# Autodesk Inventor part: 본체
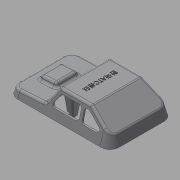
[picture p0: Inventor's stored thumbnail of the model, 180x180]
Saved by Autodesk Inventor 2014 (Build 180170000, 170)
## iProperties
Created: 2015-05
Part Number: 본체
Material: Generic
Document SubType Name: Modeling
Designer: Administrator
Density: 1 g/cm^3
Appearance: Default
Author: Administrator
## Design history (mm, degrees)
sketch "스케치2"
  geometry: L1 (-49, 38)-(49, 38); L2 (61, 26)-(61, -26); L3 (49, -38)-(-49, -38); L4 (-61, -26)-(-61, 26); L5 (-61, 38)-(61, -38); L6 (61, 38)-(-61, -38); A1 r 12 centre (-49, 26) between (-49, 38) and (-61, 26); A2 r 12 centre (-49, -26) between (-61, -26) and (-49, -38); A3 r 12 centre (49, -26) between (49, -38) and (61, -26); A4 r 12 centre (49, 26) between (61, 26) and (49, 38); 1 further point
  constraints: 12 end point, 8 point on circle, 8 point on line, 8 tangent, 4 centre point, 3 equal radius, 2 midpoint, 2 parallel, 1 horizontal, 1 perpendicular
  dimensions: "d0" = 122 distance of L5.end L6.end; "d1" = 76 distance of L6.start L5.end; "d2" = 12 radius of A1
extrude "돌출1" new body sketch "스케치2" distance "d3" = 30; taper "d4" = -15 deg
sketch "스케치3"
  geometry: L1 (-31, 30)-(-61, 30); L2 (-61, 30)-(-61, 10); L3 (-61, 10)-(-31, 30); L4 (49, 30)-(-49, 30) reference; 2 further points
  constraints: 6 end point, 1 collinear, 1 horizontal, 1 perpendicular, 1 vertical alignment
  dimensions: "d5" = 20 distance of L1.end L2.end; "d6" = 30 distance of L1.start L1.end
extrude "돌출2" cut sketch "스케치3" stored distance "d7" = 30; taper "d8" = 0 deg
sketch "스케치4"
  geometry: L1 (61, 8)-(19, 10.201); L2 (19, 10.201)-(6.628, 30); L3 (6.628, 30)-(61, 30); L4 (61, 30)-(61, 8); L5 (-49, 0)-(49, 0) reference; L6 (49, 30)-(-31, 30) reference; 3 further points
  constraints: 8 end point, 1 collinear, 1 horizontal, 1 midpoint, 1 perpendicular, 1 vertical alignment
  dimensions: "d10" = 8 distance from line of L5 L1.start; "d12" = 125 deg angle of L1 L2; "d13" = 3 deg angle of L5 L1; "d16" = 42 horizontal distance of L1.end L1.start
extrude "돌출3" cut sketch "스케치4" stored distance "d14" = 30; taper "d15" = 0 deg
sketch "스케치5"
  geometry: L1 (-39.881, 9.267)-(-39.881, 61.267) reference; L2 (-28.881, 48.267)-(-8.881, 48.267); L3 (-8.881, 48.267)-(-8.881, 22.267); L4 (-8.881, 22.267)-(-28.881, 22.267); L5 (-28.881, 22.267)-(-28.881, 48.267); 3 further points
  constraints: 8 end point, 2 midpoint, 2 parallel, 1 horizontal, 1 horizontal alignment, 1 perpendicular
  dimensions: "d17" = 11 distance between parallel lines of L1 L5; "d18" = 26 distance of L4.end L2.start; "d19" = 20 distance of L2.start L2.end
extrude "돌출4" join sketch "스케치5" distance "d20" = 5; taper "d21" = 0 deg
fillet "모깎기1" dims "d22" = 3
fillet "모깎기2" dims "d23" = 3
fillet "모깎기3" dims "d24" = 3
fillet "모깎기4" dims "d25" = 3
sketch "스케치6"
  geometry: L1 (4.965, 30)-(-30.092, 30) reference; L2 (18.172, 11.526)-(7.51, 28.59) reference; L3 (-31.756, 29.496)-(-50.664, 16.891) reference; L4 (2.194, 25)-(-17.77, 25); L5 (10.362, 14.59)-(4.738, 23.59); L6 (7.818, 10)-(-17.77, 10); L7 (-20.77, 13)-(-20.77, 22); L8 (-30.242, 24.496)-(-43.742, 15.496); L9 (-28.578, 25)-(-26.986, 25); L10 (-23.986, 22)-(-23.986, 13); L11 (-26.986, 10)-(-42.078, 10); A1 r 3 centre (7.818, 13) between (7.818, 10) and (10.362, 14.59); A2 r 3 centre (2.194, 22) between (4.738, 23.59) and (2.194, 25); A3 r 3 centre (-17.77, 22) between (-17.77, 25) and (-20.77, 22); A4 r 3 centre (-17.77, 13) between (-20.77, 13) and (-17.77, 10); A5 r 3 centre (-26.986, 13) between (-26.986, 10) and (-23.986, 13); A6 r 3 centre (-26.986, 22) between (-23.986, 22) and (-26.986, 25); A7 r 3 centre (-28.578, 22) between (-28.578, 25) and (-30.242, 24.496); A8 r 3 centre (-42.078, 13) between (-43.742, 15.496) and (-42.078, 10); 7 further points
  constraints: 16 end point, 16 point on circle, 16 tangent, 12 point on line, 8 centre point, 7 equal radius, 5 parallel, 3 perpendicular
  dimensions: "d26" = 5 distance between parallel lines of L4 L1; "d27" = 5 distance between parallel lines of L5 L2; "d28" = 34 distance of point (13.23, 10) point (-20.77, 10); "d29" = 15 distance of point (-20.77, 25) point (-20.77, 10); "d30" = 5 distance between parallel lines of L8 L3; "d31" = 5 distance between parallel lines of L9 L1; "d32" = 15 distance of point (-23.986, 25) point (-23.986, 10); "d33" = 28 distance of point (-51.986, 10) point (-23.986, 10); "d35" = 3 radius of A1
sketch "스케치7"
  geometry: L1 (61, 26)-(61, -26) reference; L2 (-49, 38)-(49, 38) reference; L3 (-61, -26)-(-61, 26) reference; L4 (49, -38)-(-49, -38) reference; A1 r 12 centre (49, 26) between (61, 26) and (49, 38) reference; A2 r 12 centre (-49, 26) between (-49, 38) and (-61, 26) reference; A3 r 12 centre (-49, -26) between (-61, -26) and (-49, -38) reference; A4 r 12 centre (49, -26) between (49, -38) and (61, -26) reference; 1 further point
feature "쉘1" dims "d34" = 2
extrude "돌출5" cut sketch "스케치6" stored distance "d36" = 5; taper "d37" = 0 deg
node "작업 평면1"
sketch "스케치8"
  geometry: A1 r 4 centre (21, 0) between (25, 0) and (17, 0); A2 r 4 centre (10, 0) between (14, 0) and (6, 0); 3 further points
  constraints: 4 point on circle, 2 centre point, 7 other
  dimensions: "d39" = 4 radius of A1; "d40" = 4 radius of A2; "d41" = 10 distance of A2.centre point (0, 0); "d42" = 11 distance of A2.centre A1.centre
extrude "돌출6" join sketch "스케치8" stored distance "d43" = 5; taper "d44" = 0 deg
chamfer "모따기1" distance "d45" = 1; stored, may be unused: second distance "d46" = 2, angle "d47" = 45 deg
sketch "스케치9"
  geometry: L1 (-4.965, -27.66)-(-4.965, 27.66) reference; L2 (61, -26)-(61, 26) reference; 3 further points
  constraints: 1 horizontal alignment, 1 midpoint, 1 other
  dimensions: "d48" = 50 distance from line of L2 point (11, 0)
feature "엠보싱1" sketch "스케치9" dims "d0" = 122, "d1" = 76, "d2" = 12, "d49" = 0.5, "d50" = 0
sketch "스케치10"
  geometry: L1 (58.929, 26)-(58.929, -26) reference; L2 (49, -35.929)-(-49, -35.929) reference; L3 (-58.929, -26)-(-58.929, 26) reference; L4 (-49, 35.929)-(49, 35.929) reference; L5 (49, 36.929)-(-49, 36.929); L6 (-59.929, 26)-(-59.929, -26); L7 (-49, -36.929)-(49, -36.929); L8 (59.929, -26)-(59.929, 26); A1 r 9.929 centre (49, -26) between (49, -35.929) and (58.929, -26) reference; A2 r 9.929 centre (-49, -26) between (-58.929, -26) and (-49, -35.929) reference; A3 r 9.929 centre (-49, 26) between (-49, 35.929) and (-58.929, 26) reference; A4 r 9.929 centre (49, 26) between (58.929, 26) and (49, 35.929) reference; A5 r 10.929 centre (-49, 26) between (-49, 36.929) and (-59.929, 26); A6 r 10.929 centre (-49, -26) between (-59.929, -26) and (-49, -36.929); A7 r 10.929 centre (49, -26) between (49, -36.929) and (59.929, -26); A8 r 10.929 centre (49, 26) between (59.929, 26) and (49, 36.929); 1 further point
  constraints: 8 end point, 8 point on circle, 4 centre point, 7 other
  dimensions: "d51" = 1 distance between parallel lines of L4 L5
extrude "돌출7" join sketch "스케치10" distance "d52" = 1; taper "d53" = 0 deg
sketch "스케치11"
  geometry: C1 r 3 at (0, 22); C2 r 3 at (-40, 0); C3 r 3 at (0, -22); C4 r 3 at (40, 0); 1 further point
  constraints: 4 centre point, 2 horizontal alignment, 2 vertical alignment
  dimensions: "d54" = 6 diameter of C3; "d55" = 6 diameter of C1; "d56" = 6 diameter of C2; "d57" = 6 diameter of C4; "d58" = 22 distance of C1.centre point (0, 0); "d59" = 44 distance of C1.centre C3.centre; "d60" = 40 distance of point (0, 0) C4.centre; "d61" = 40 distance of point (0, 0) C2.centre
extrude "돌출8" join sketch "스케치11" stored distance "d62" = 1; taper "d63" = 2 deg
node "작업 평면2"
sketch "스케치12"
  geometry: L1 (-44.994, -1)-(-34.994, -1); L2 (-34.994, -1)-(-34.994, 1); L3 (-34.994, 1)-(-44.994, 1); L4 (-44.994, 1)-(-44.994, -1); L5 (-44.994, -1)-(-34.994, 1); L6 (-34.994, -1)-(-44.994, 1); L7 (-5, 21)-(5, 21); L8 (5, 21)-(5, 23); L9 (5, 23)-(-5, 23); L10 (-5, 23)-(-5, 21); L11 (-5, 21)-(5, 23); L12 (5, 21)-(-5, 23); L13 (34.913, -1)-(44.913, -1); L14 (44.913, -1)-(44.913, 1); L15 (44.913, 1)-(34.913, 1); L16 (34.913, 1)-(34.913, -1); L17 (34.913, -1)-(44.913, 1); L18 (44.913, -1)-(34.913, 1); L19 (-5, -23)-(5, -23); L20 (5, -23)-(5, -21); L21 (5, -21)-(-5, -21); L22 (-5, -21)-(-5, -23); L23 (-5, -23)-(5, -21); L24 (5, -23)-(-5, -21); C1 r 3.978 at (0, -22) reference; C2 r 3.978 at (0, 22) reference; 3 further points; 2 other entities
  constraints: 48 end point, 8 midpoint, 8 parallel, 4 horizontal, 4 perpendicular, 2 other
  dimensions: "d65" = 2 distance of L1.end L2.end; "d66" = 10 distance of L2.end L3.end; "d67" = 10 distance of L7.start L7.end; "d68" = 2 distance of L7.end L8.end; "d69" = 10 distance of L14.end L15.end; "d70" = 2 distance of L13.end L14.end; "d71" = 10 distance of L20.end L21.end; "d72" = 2 distance of L19.end L20.end
extrude "돌출9" join sketch "스케치12" stored distance "d73" = 2; taper "d74" = 2.5 deg
sketch "스케치18"
  geometry: C1 r 3 at (0, 0) reference; C2 r 3 at (-40, 22) reference; C3 r 3 at (0, 44) reference; C4 r 3 at (40, 22) reference; 5 further points
  constraints: 4 coincident
hole "구멍1" sketch "스케치18" at (-40, 22), (0, 0), (40, 22), (0, 44) diameter "d94" = 3.242; stored, may be unused: countersink angle "d98" = 90 deg, drill point angle "d100" = 118 deg; dims "d95" = 9, "d96" = 4, "d97" = 2, "d99" = 11
sketch "스케치19"
  geometry: L1 (34.994, 2)-(34.54, 12.391) reference; L2 (31.021, 12.575)-(45.002, 11.843) reference; L3 (44.994, 2)-(45.42, 11.762) reference; L4 (-30.092, 30)-(4.965, 30) reference; L5 (34.994, 2)-(33.149, 12.464); L6 (44.994, 2)-(46.348, 9.68); A1 r 5 centre (50.994, 11.529) between (46.027, 10.954) and (50.732, 6.535) reference; A2 r 1 centre (45.034, 10.84) between (46.027, 10.954) and (45.086, 11.838) reference; 1 further point
  constraints: 4 end point, 1 point on circle, 1 point on line
  dimensions: "d101" = 80 deg angle of L4 L5; "d102" = 100 deg angle of L4 L6
extrude "돌출15" join sketch "스케치19" stored distance "d103" = 2; taper "d104" = 0 deg
sketch "스케치20"
  geometry: L1 (-44.913, 2)-(-45.605, 17.86) reference; L2 (-34.913, 2)-(-33.879, 25.677) reference; L3 (-30.092, 30)-(4.965, 30) reference; L4 (-34.913, 2)-(-30.333, 27.97); L5 (-44.913, 2)-(-47.488, 16.604); L6 (-49.555, 15.226)-(-30.646, 27.832) reference; A1 r 1 centre (-30.092, 27) between (-30.092, 28) and (-30.646, 27.832) reference; 1 further point
  constraints: 4 end point, 1 point on circle, 1 point on line
  dimensions: "d105" = 80 deg angle of L4 L3; "d106" = 100 deg angle of L5 L3
extrude "돌출16" join sketch "스케치20" stored distance "d107" = 2; taper "d108" = 0 deg
node "작업 평면3"
sketch "스케치21"
  geometry: L1 (-5, 2)-(-6.135, 28) reference; L2 (5, 2)-(6.095, 27.079) reference; L3 (-30.092, 30)-(4.965, 30) reference; L4 (-5, 2)-(-9.585, 28); L5 (5, 2)-(8.69, 22.927); L6 (5.813, 27.53)-(16.476, 10.466) reference; L7 (-30.092, 28)-(4.965, 28) reference; 1 further point
  constraints: 4 end point, 2 point on line
  dimensions: "d110" = 100 deg angle of L5 L3; "d111" = 100 deg angle of L3 L4
extrude "돌출17" join sketch "스케치21" stored distance "d112" = 2; taper "d113" = 0 deg
node "작업 평면4"
sketch "스케치22"
  geometry: L1 (-5, 2)-(-6.135, 28) reference; L2 (5, 2)-(6.095, 27.079) reference; L3 (-30.092, 30)-(4.965, 30) reference; L4 (-5, 2)-(-9.585, 28); L5 (5, 2)-(8.69, 22.927); L6 (5.813, 27.53)-(16.476, 10.466) reference; L7 (-30.092, 28)-(4.965, 28) reference; 1 further point
  constraints: 4 end point, 2 point on line
  dimensions: "d115" = 100 deg angle of L5 L3; "d116" = 100 deg angle of L3 L4
extrude "돌출18" join sketch "스케치22" stored distance "d117" = 0; taper "d118" = 0 deg
node "솔리드1"
mirror "대칭1"
node "투영된 루프2"
node "투영된 루프3"
node "투영된 루프4"
other parameters: "d38" = -63, "d64" = 2, "d109" = 22, "d114" = -22
